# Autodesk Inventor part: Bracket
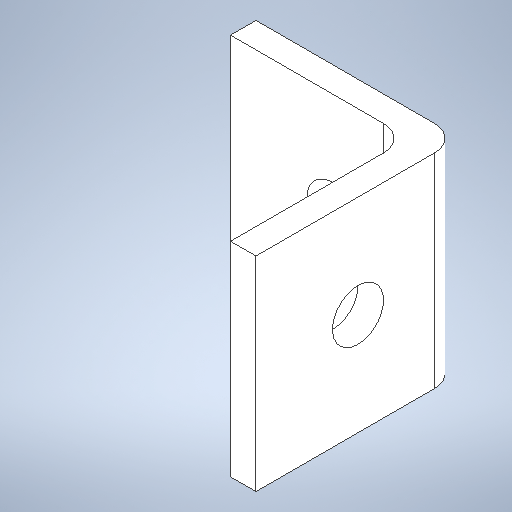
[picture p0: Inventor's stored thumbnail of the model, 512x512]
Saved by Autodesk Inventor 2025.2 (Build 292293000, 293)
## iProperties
Created: 2025-09
Part Number: Bracket
Material: Generic
Document SubType Name: Modeling
Designer: tyler
Density: 1 g/cm^3
Appearance: Default
Author: tyler
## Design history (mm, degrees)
sketch "Sketch1"
  geometry: 1 further point
sketch "Sketch2"
  geometry: L1 (0, 3.175)-(0, 22.225); L2 (3.175, 0)-(22.225, 0); L3 (22.225, 0)-(22.225, -3.175); L4 (22.225, -3.175)-(0, -3.175); L5 (-3.175, 0)-(-3.175, 22.225); L6 (-3.175, 22.225)-(0, 22.225); A1 r 3.175 centre (3.175, 3.175) between (0, 3.175) and (3.175, 0); A2 r 3.175 centre (0, 0) between (-3.175, 0) and (0, -3.175); 2 further points
  constraints: 12 end point, 4 perpendicular, 4 point on circle, 4 point on line, 4 tangent, 2 centre point, 1 equal radius, 1 horizontal, 1 vertical
  dimensions: "d0" = 22.225 distance of point (0, 0) L1.end; "d1" = 22.225 distance of point (0, 0) L2.end; "d2" = 3.175 distance of L2.end L3.end; "d3" = 25.4 distance of L3.end point (-3.175, -3.175); "d4" = 3.175 radius of A1 (derived)
extrude "Extrusion1" new body sketch "Sketch2" distance "d5" = 25.4; taper "d6" = 0 deg
sketch "Sketch3"
  geometry: L1 (0, 0)-(0, 25.4) reference; L2 (0, 12.7)-(12.7, 12.7); C1 r 3.175 at (12.7, 12.7); 1 further point
  constraints: 2 end point, 1 centre point, 1 coincident, 1 horizontal, 1 midpoint
  dimensions: "d8" = 12.7 distance of L2.start L2.end; "d9" = 6.35 diameter of C1
extrude "Extrusion2" cut sketch "Sketch3" distance "d10" = 25.4; taper "d11" = 0 deg
sketch "Sketch4"
  geometry: L1 (19.05, 0)-(19.05, 25.4) reference; L2 (19.05, 12.7)-(6.35, 12.7); C1 r 3.175 at (6.35, 12.7); 1 further point
  constraints: 2 end point, 1 centre point, 1 coincident, 1 horizontal, 1 midpoint
  dimensions: "d12" = 12.7 distance of L2.start L2.end; "d13" = 6.35 diameter of C1
extrude "Extrusion3" cut sketch "Sketch4" distance "d14" = 25.4; taper "d15" = 0 deg
body "Solid1"
